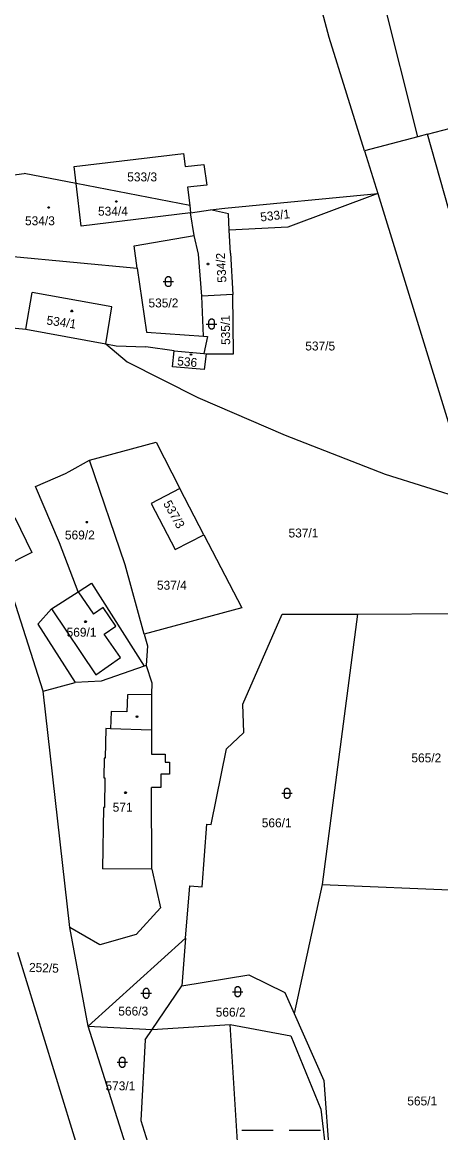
# Model space of a CAD drawing. Extents: x -812394 to -807601, y -1013097 to -1009266.
# Drawn here: x -809083.2 to -809003.5, y -1011807.5 to -1011595.7 of the extents above; entities that cross this region are included whole.
import ezdxf

# ---------------------------------------------------------------- set-up
doc = ezdxf.new("R2010")
doc.units = 0
for name, color, linetype in [('Default', 7, 'Continuous'), ('KN_HRANICE', 7, 'Continuous'), ('KN_KULTURY', 7, 'Continuous'), ('KN_PARCELY', 7, 'Continuous'), ('KN_SLUCKY', 7, 'Continuous')]:
    doc.layers.add(name, color=color, linetype=linetype)

# ---------------------------------------------------------------- blocks, each defined once
blk = doc.blocks.new('316')
at = {"layer": 'Default'}
for points in [[(-1, 1), (0.27, 1), (1, 1)], [(-0.5, 1.5), (-0.4, 1.79), (-0.15, 1.97), (0.16, 1.97), (0.41, 1.79), (0.51, 1.5), (0.51, 0.5), (0.41, 0.21), (0.16, 0.03), (-0.15, 0.03), (-0.4, 0.21), (-0.5, 0.5), (-0.5, 1.5)]]:
    blk.add_lwpolyline(points, dxfattribs=at)
blk = doc.blocks.new('NAHRADNI_SYMBOL')
at = {"layer": 'Default'}
blk.add_lwpolyline([(0.09, 0.15), (0.18, 0), (0.09, -0.15), (-0.09, -0.15), (-0.18, 0), (-0.09, 0.15), (0.09, 0.15)], dxfattribs=at)
blk = doc.blocks.new('803')
at = {"layer": 'Default'}
for p, q in [((-7.5, 0), (-1.5, 0)), ((1.5, 0), (7.5, 0))]:
    blk.add_line(p, q, dxfattribs=at)
blk = doc.blocks.new('402')
at = {"layer": 'Default'}
blk.add_lwpolyline([(0.09, 0.15), (0.18, 0), (0.09, -0.15), (-0.09, -0.15), (-0.18, 0), (-0.09, 0.15), (0.09, 0.15)], dxfattribs=at)

msp = doc.modelspace()

# ---------------------------------------------------------------- linework, layer by layer
at = {"layer": 'KN_HRANICE'}
for p, q in [((-809024.74, -1011598.61), (-809038.36, -1011547.76)), ((-809007.85, -1011617.52), (-809019.32, -1011571.78)), ((-809018.04, -1011620.2), (-809024.74, -1011598.61)), ((-809006.01, -1011617.04), (-808975.11, -1011608.93)), ((-809006.01, -1011617.04), (-809007.85, -1011617.52)), ((-809002.01, -1011631.2), (-809006.01, -1011617.04)), ((-809007.85, -1011617.52), (-809018.04, -1011620.2)), ((-809073.36, -1011623.22), (-809052.52, -1011620.7)), ((-809052.52, -1011620.7), (-809052.22, -1011623.16)), ((-809018.04, -1011620.2), (-809015.5, -1011628.37)), ((-809072.97, -1011626.45), (-809073.36, -1011623.22)), ((-809052.22, -1011623.16), (-809048.61, -1011622.78)), ((-809048.61, -1011622.78), (-809048.07, -1011626.76)), ((-809087.79, -1011625.14), (-809082.89, -1011624.52)), ((-809072.97, -1011626.45), (-809082.89, -1011624.52)), ((-809051.31, -1011630.65), (-809072.97, -1011626.45)), ((-809071.99, -1011634.54), (-809072.97, -1011626.45)), ((-809048.07, -1011626.76), (-809051.74, -1011627.11)), ((-809051.74, -1011627.11), (-809051.31, -1011630.65)), ((-809044.66, -1011631.11), (-809015.5, -1011628.37)), ((-809015.5, -1011628.37), (-809032.61, -1011634.74)), ((-809015.5, -1011628.37), (-808997.45, -1011687.11)), ((-809051.31, -1011630.65), (-809051.15, -1011632.01)), ((-809051.15, -1011632.01), (-809047.34, -1011631.48)), ((-809047.34, -1011631.48), (-809044.66, -1011631.11)), ((-809043.93, -1011632.19), (-809047.34, -1011631.48)), ((-809051.15, -1011632.01), (-809071.99, -1011634.54)), ((-809050.46, -1011636.33), (-809051.15, -1011632.01)), ((-809043.78, -1011635.36), (-809043.93, -1011632.19)), ((-809032.61, -1011634.74), (-809043.78, -1011635.36)), ((-809043.57, -1011639.69), (-809043.78, -1011635.36)), ((-809061.88, -1011638.33), (-809050.46, -1011636.33)), ((-809049.65, -1011639.88), (-809050.46, -1011636.33)), ((-809085.58, -1011640.3), (-809061.33, -1011642.55)), ((-809061.33, -1011642.55), (-809061.88, -1011638.33)), ((-809049.03, -1011647.94), (-809049.65, -1011639.88)), ((-809043.57, -1011639.69), (-809043.09, -1011647.59)), ((-809061.33, -1011642.55), (-809059.57, -1011654.76)), ((-809043.09, -1011647.59), (-809049.03, -1011647.94)), ((-809048.69, -1011655.54), (-809049.03, -1011647.94)), ((-809042.98, -1011658.92), (-809043.09, -1011647.59)), ((-809085.85, -1011653.87), (-809082.52, -1011654.22)), ((-809082.52, -1011654.22), (-809067.32, -1011657.02)), ((-809059.57, -1011654.76), (-809048.69, -1011655.54)), ((-809067.32, -1011657.02), (-809063.24, -1011660.46)), ((-809067.32, -1011657.02), (-809065.36, -1011657.38)), ((-809048.69, -1011655.54), (-809047.95, -1011655.61)), ((-809047.95, -1011655.61), (-809048.64, -1011658.88)), ((-809065.36, -1011657.38), (-809059.71, -1011657.61)), ((-809054.31, -1011658.32), (-809059.71, -1011657.61)), ((-809054.58, -1011661.43), (-809054.31, -1011658.32)), ((-809054.31, -1011658.32), (-809048.64, -1011658.88)), ((-809048.64, -1011658.88), (-809048.2, -1011658.92)), ((-809048.2, -1011658.92), (-809048.58, -1011661.92)), ((-809048.2, -1011658.92), (-809042.98, -1011658.92)), ((-809063.24, -1011660.46), (-809049.78, -1011667.23)), ((-809048.58, -1011661.92), (-809054.58, -1011661.43)), ((-809049.78, -1011667.23), (-809033.12, -1011674.42)), ((-809070.44, -1011679.2), (-809057.74, -1011675.8)), ((-809057.74, -1011675.8), (-809053.23, -1011684.62)), ((-809033.12, -1011674.42), (-809014.11, -1011681.87)), ((-809074.31, -1011681.39), (-809070.44, -1011679.2)), ((-809063.59, -1011699.18), (-809070.44, -1011679.2)), ((-809080.69, -1011684.21), (-809074.99, -1011681.77)), ((-809074.99, -1011681.77), (-809074.31, -1011681.39)), ((-809014.11, -1011681.87), (-808997.45, -1011687.11)), ((-809076.1, -1011694.95), (-809080.69, -1011684.21)), ((-809053.23, -1011684.62), (-809058.69, -1011687.46)), ((-809048.65, -1011693.42), (-809053.23, -1011684.62)), ((-809058.69, -1011687.46), (-809054.11, -1011696.26)), ((-809084.66, -1011690.15), (-809081.39, -1011696.85)), ((-809072.55, -1011704.3), (-809076.1, -1011694.95)), ((-809054.11, -1011696.26), (-809048.65, -1011693.42)), ((-809048.65, -1011693.42), (-809041.37, -1011707.4)), ((-809081.39, -1011696.85), (-809086.82, -1011699.58)), ((-809079.24, -1011723.27), (-809086.82, -1011699.58)), ((-809059.99, -1011712.39), (-809063.59, -1011699.18)), ((-809072.55, -1011704.3), (-809070.01, -1011702.67)), ((-809070.01, -1011702.67), (-809060.03, -1011718.52)), ((-809077.65, -1011707.56), (-809072.55, -1011704.3)), ((-809080.26, -1011710.48), (-809077.65, -1011707.56)), ((-809041.37, -1011707.4), (-809059.99, -1011712.39)), ((-809041.21, -1011725.74), (-809033.74, -1011708.6)), ((-809033.74, -1011708.6), (-809019.35, -1011708.55)), ((-809019.35, -1011708.55), (-809026.09, -1011760.16)), ((-809019.35, -1011708.55), (-808992.34, -1011708.44)), ((-809080.26, -1011710.48), (-809073.13, -1011721.6)), ((-809059.99, -1011712.39), (-809059.38, -1011714.65)), ((-809059.38, -1011714.65), (-809059.65, -1011718.39)), ((-809060.03, -1011718.52), (-809068.19, -1011721.35)), ((-809059.65, -1011718.39), (-809060.03, -1011718.52)), ((-809059.65, -1011718.39), (-809058.51, -1011721.71)), ((-809079.24, -1011723.27), (-809073.13, -1011721.6)), ((-809068.19, -1011721.35), (-809073.13, -1011721.6)), ((-809058.51, -1011721.71), (-809058.62, -1011723.92)), ((-809074.17, -1011768.37), (-809079.24, -1011723.27)), ((-809058.62, -1011723.92), (-809058.6, -1011730.69)), ((-809040.99, -1011731.14), (-809041.21, -1011725.74)), ((-809058.6, -1011730.69), (-809058.59, -1011735.29)), ((-809044.31, -1011734.3), (-809040.99, -1011731.14)), ((-809058.59, -1011735.29), (-809055.99, -1011735.28)), ((-809055.99, -1011735.28), (-809055.99, -1011736.83)), ((-809047.24, -1011748.72), (-809044.31, -1011734.3)), ((-809055.99, -1011736.83), (-809055.19, -1011736.83)), ((-809055.19, -1011736.83), (-809055.18, -1011739.08)), ((-809055.18, -1011739.08), (-809056.83, -1011739.09)), ((-809056.83, -1011739.09), (-809056.83, -1011741.64)), ((-809056.83, -1011741.64), (-809058.58, -1011741.64)), ((-809058.55, -1011757.24), (-809058.58, -1011741.64)), ((-809048.93, -1011760.57), (-809048.08, -1011748.66)), ((-809048.08, -1011748.66), (-809047.24, -1011748.72)), ((-809058.55, -1011757.24), (-809056.9, -1011764.63)), ((-809052.13, -1011770.41), (-809051.33, -1011760.4)), ((-809051.33, -1011760.4), (-809048.93, -1011760.57)), ((-809026.09, -1011760.16), (-809031.43, -1011784.75)), ((-809026.09, -1011760.16), (-808975.59, -1011762.27)), ((-809056.9, -1011764.63), (-809061.5, -1011769.71)), ((-809070.64, -1011787.15), (-809074.17, -1011768.37)), ((-809068.47, -1011771.64), (-809074.17, -1011768.37)), ((-809070.64, -1011787.15), (-809052.13, -1011770.41)), ((-809061.5, -1011769.71), (-809068.47, -1011771.64)), ((-809052.13, -1011770.41), (-809052.85, -1011779.47)), ((-809068.2, -1011824.99), (-809084.06, -1011773.13)), ((-809052.85, -1011779.47), (-809040.06, -1011777.39)), ((-809040.06, -1011777.39), (-809033.21, -1011780.74)), ((-809058.49, -1011787.83), (-809052.85, -1011779.47)), ((-809033.21, -1011780.74), (-809031.43, -1011784.75)), ((-809031.43, -1011784.75), (-809025.76, -1011797.55)), ((-809070.64, -1011787.15), (-809058.49, -1011787.83)), ((-809059.59, -1011822.15), (-809070.64, -1011787.15)), ((-809059.83, -1011789.81), (-809058.49, -1011787.83)), ((-809058.49, -1011787.83), (-809043.65, -1011786.86)), ((-809043.65, -1011786.86), (-809032.04, -1011789.04)), ((-809039.91, -1011846.09), (-809043.65, -1011786.86)), ((-809059.83, -1011789.81), (-809060.63, -1011805.19)), ((-809032.04, -1011789.04), (-809026.36, -1011802.99)), ((-809025.76, -1011797.55), (-809023.89, -1011823.5)), ((-809026.36, -1011802.99), (-809023.89, -1011823.5)), ((-809060.63, -1011805.19), (-809052.86, -1011830.28))]:
    msp.add_line(p, q, dxfattribs=at)
at = {"layer": 'KN_SLUCKY'}
for p, q in [((-809082.52, -1011654.22), (-809081.34, -1011647.24)), ((-809066.17, -1011649.93), (-809081.34, -1011647.24)), ((-809067.32, -1011657.02), (-809066.17, -1011649.93)), ((-809072.55, -1011704.3), (-809069.64, -1011708.56)), ((-809077.65, -1011707.56), (-809069.21, -1011720.16)), ((-809067.82, -1011707.33), (-809069.64, -1011708.56)), ((-809065.41, -1011710.9), (-809067.82, -1011707.33)), ((-809067.6, -1011712.38), (-809065.41, -1011710.9)), ((-809064.48, -1011716.84), (-809067.6, -1011712.38)), ((-809069.21, -1011720.16), (-809064.48, -1011716.84)), ((-809063.19, -1011723.98), (-809063.29, -1011727.23)), ((-809058.62, -1011723.92), (-809063.19, -1011723.98)), ((-809066.29, -1011727.14), (-809066.39, -1011730.44)), ((-809063.29, -1011727.23), (-809066.29, -1011727.14)), ((-809067.33, -1011730.41), (-809067.42, -1011736.07)), ((-809066.39, -1011730.44), (-809067.33, -1011730.41)), ((-809058.6, -1011730.69), (-809066.39, -1011730.44)), ((-809067.62, -1011736.07), (-809067.67, -1011739.78)), ((-809067.42, -1011736.07), (-809067.62, -1011736.07)), ((-809067.67, -1011739.78), (-809067.47, -1011739.78)), ((-809067.47, -1011739.78), (-809067.56, -1011745.49)), ((-809067.76, -1011745.49), (-809067.94, -1011757.16)), ((-809067.56, -1011745.49), (-809067.76, -1011745.49)), ((-809058.55, -1011757.24), (-809067.94, -1011757.16))]:
    msp.add_line(p, q, dxfattribs=at)

# ---------------------------------------------------------------- block references
at = {"layer": 'KN_KULTURY'}
for name, p in [('NAHRADNI_SYMBOL', (-809065.3, -1011629.86)), ('NAHRADNI_SYMBOL', (-809078.2, -1011631.01)), ('NAHRADNI_SYMBOL', (-809047.84, -1011641.77)), ('316', (-809055.41, -1011646.14)), ('402', (-809073.78, -1011650.74)), ('316', (-809047.16, -1011654.24)), ('402', (-809051.08, -1011659.05)), ('NAHRADNI_SYMBOL', (-809070.92, -1011691.03)), ('402', (-809071.16, -1011710)), ('402', (-809061.37, -1011728.13)), ('316', (-809032.79, -1011743.75)), ('402', (-809063.54, -1011742.62)), ('316', (-809059.62, -1011781.9)), ('316', (-809042.19, -1011781.6)), ('316', (-809064.17, -1011795.07)), ('803', (-809033.9, -1011806.98))]:
    msp.add_blockref(name, p, dxfattribs=at)

# ---------------------------------------------------------------- texts
at = {"layer": 'KN_PARCELY'}
for s, p in [('533/3', (-809063.23, -1011626.03)), ('534/4', (-809068.79, -1011632.57)), ('534/3', (-809082.7, -1011634.39)), ('535/2', (-809059.18, -1011650.07)), ('537/5', (-809029.31, -1011658.28)), ('569/2', (-809075.1, -1011694.33)), ('537/1', (-809032.5, -1011693.95)), ('537/4', (-809057.57, -1011703.92)), ('569/1', (-809074.78, -1011712.88)), ('565/2', (-809009.1, -1011736.85)), ('571', (-809066, -1011746.26)), ('566/1', (-809037.6, -1011749.24)), ('566/3', (-809064.93, -1011785.15)), ('566/2', (-809046.37, -1011785.35)), ('573/1', (-809067.38, -1011799.41)), ('565/1', (-809009.88, -1011802.29))]:
    msp.add_text(s, height=1.7, dxfattribs=at).set_placement(p)
for s, rotation, p in [('533/1', 6.589, (-809037.79, -1011633.69)), ('534/2', 93.449, (-809044.31, -1011645.28)), ('534/1', 351.739, (-809078.69, -1011653.31)), ('535/1', 90.871, (-809043.61, -1011657.21)), ('536', 354.89, (-809053.76, -1011661.12)), ('537/3', 299.256, (-809056.43, -1011687.47)), ('252/5', 357.927, (-809081.97, -1011776.79))]:
    msp.add_text(s, height=1.7, rotation=rotation, dxfattribs=at).set_placement(p)

doc.saveas('drawing.dxf')
